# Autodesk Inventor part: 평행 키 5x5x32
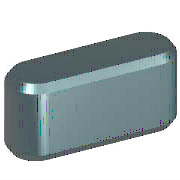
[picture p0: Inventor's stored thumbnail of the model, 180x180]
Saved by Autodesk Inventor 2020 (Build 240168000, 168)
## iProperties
Created: 2012-02
Part Number: 평행 키 5x5x32
Material: 강철, 연강
Description: 평행 키
Document SubType Name: Modeling
Standard: JIS B 1301
Designer: mdu-01
Standards Organization: JIS
Language: ko-KR
Size Designation: 5x5x32
Categories: <MemberInstance><Categories><Category DisplayName="샤프트 부품" InternalName="7f7aeb1f-a693-4053-b835-cee3144e0d98" Mnemonic="SHFT"><Category DisplayName="키" Interna
Density: 1 g/cm^3
Appearance: 기본값(2)
IsCustomPart: 1
Author: mdu-01
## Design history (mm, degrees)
workplane "Work Plane1"
workplane "Work Plane2"
sketch "스케치1"
  geometry: L1 (2.5, 2.5)-(29.5, 2.5); L2 (29.5, -2.5)-(2.5, -2.5); L3 (0, 9.4)-(0, -7.4) reference; L4 (-5, 0)-(30, 0) reference; L5 (32, 0)-(32, 7); A1 r 2.5 centre (2.5, 0) between (2.5, 2.5) and (2.5, -2.5); A2 r 2.5 centre (29.5, 0) between (29.5, -2.5) and (29.5, 2.5)
  constraints: 6 end point, 5 point on circle, 4 tangent, 3 point on line, 2 centre point, 1 horizontal, 1 parallel, 1 perpendicular
  dimensions: "d0" = 2.5 radius of A1 (= 0.5 x PB); "d13" = 2.5 radius of A2 (= 0.5 x PB); "d14" = 32 distance between parallel lines of L5 L3 (= NLG)
extrude "본체1" new body sketch "스케치1" taper "d3" = 0 deg; stored distance "d4" = 10
workplane "Work Plane3"
body "Solid1"
chamfer "모따기1" distance "d8" = 0.4 (= PHH); stored, may be unused: second distance "d9" = 0.4 (= PHH), angle "d15" = 45 deg
other parameters: "d1" = -3 (= -PNT), "d2" = 2 (= PH - PNT), "NLG" = 32 [user parameter; used in 3 equation terms], "PB" = 5 [user parameter; used in 2 equation terms], "PNT" = 3 [user parameter; used in 2 equation terms], "PH" = 5 [user parameter; used in 1 equation term], "PHH" = 0.4 [user parameter; used in 2 equation terms], "d10" = 0, "d16" = 0, "d17" = 0, "d18" = 0, "WDMIN" = 12 [user parameter], "PLB2" = 32 (= NLG) [user parameter], "WDMAX" = 17 [user parameter], "PLB1" = 32 (= NLG) [user parameter], "RR" = 0.16 [user parameter], "PUEB" = 2.3 [user parameter]
